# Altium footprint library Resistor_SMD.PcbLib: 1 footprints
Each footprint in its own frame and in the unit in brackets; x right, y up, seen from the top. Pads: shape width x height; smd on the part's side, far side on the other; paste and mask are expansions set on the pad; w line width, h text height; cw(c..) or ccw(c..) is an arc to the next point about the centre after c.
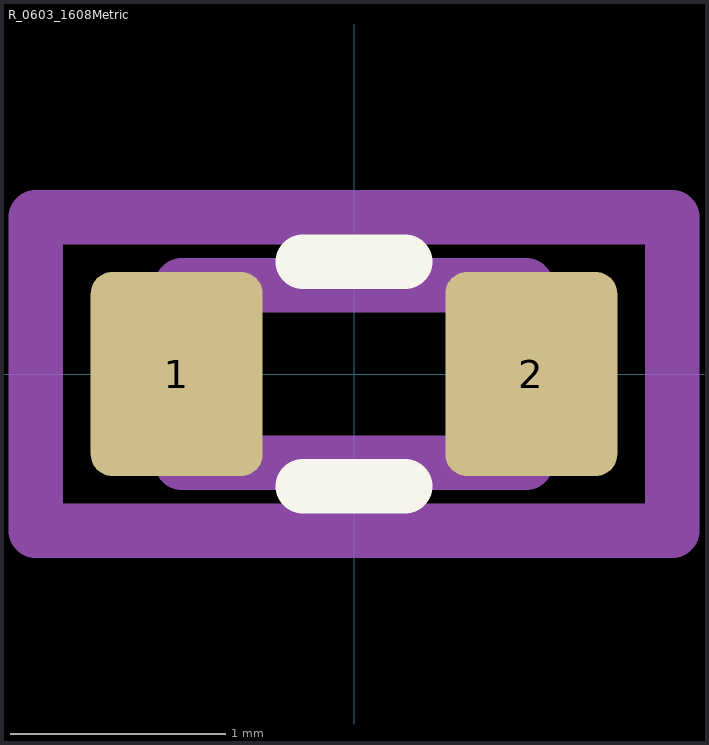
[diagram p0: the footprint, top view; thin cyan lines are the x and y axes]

## R_0603_1608Metric [mm]
pads (2):
  rrect25% 0.8x0.95 smd: 1(-0.825,0) 2(0.825,0)
F.SilkS:
  lines w0.254: -0.237,-0.523 0.237,-0.523 ; -0.237,0.523 0.237,0.523
F.CrtYd:
  lines w0.254: -1.48,-0.73 -1.48,0.73 1.48,0.73 1.48,-0.73 -1.48,-0.73
F.Fab:
  lines w0.254: -0.8,-0.413 -0.8,0.413 0.8,0.413 0.8,-0.413 -0.8,-0.413
  text "'.Designator'" at -1.619,-0.336 h0.4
